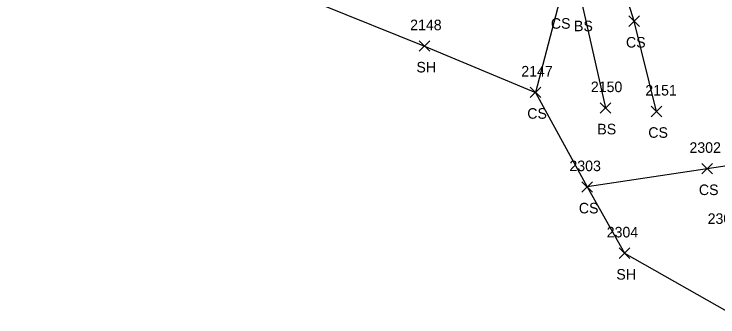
# Model space of a CAD drawing. Extents: x 1512665 to 1513714, y 110636 to 112816.
# Drawn here: x 1512781.5 to 1512914.5, y 110708.3 to 110765.6 of the extents above; entities that cross this region are included whole.
import ezdxf

# ---------------------------------------------------------------- set-up
doc = ezdxf.new("R2010")
doc.units = 0
for name, color, linetype in [('L_A', 7, 'Continuous'), ('L_I', 7, 'Continuous'), ('L_TIC', 7, 'Continuous'), ('LELB', 7, 'Continuous'), ('LSOGP', 7, 'Continuous')]:
    doc.layers.add(name, color=color, linetype=linetype)

msp = doc.modelspace()

# ---------------------------------------------------------------- linework, layer by layer
at = {"layer": 'L_TIC'}
for points in [[(1512897.68, 110763.29), (1512899.68, 110765.29)], [(1512899.68, 110763.29), (1512897.68, 110765.29)], [(1512858.02, 110758.58), (1512860.02, 110760.58)], [(1512860.02, 110758.58), (1512858.02, 110760.58)], [(1512879.03, 110749.81), (1512881.03, 110751.81)], [(1512881.03, 110749.81), (1512879.03, 110751.81)], [(1512892.27, 110746.85), (1512894.27, 110748.85)], [(1512894.27, 110746.85), (1512892.27, 110748.85)], [(1512901.91, 110746.2), (1512903.91, 110748.2)], [(1512903.91, 110746.2), (1512901.91, 110748.2)], [(1512911.47, 110735.35), (1512913.47, 110737.35)], [(1512913.47, 110735.35), (1512911.47, 110737.35)], [(1512888.78, 110731.88), (1512890.78, 110733.88)], [(1512890.78, 110731.88), (1512888.78, 110733.88)], [(1512895.83, 110719.33), (1512897.83, 110721.33)], [(1512897.83, 110719.33), (1512895.83, 110721.33)]]:
    msp.add_lwpolyline(points, dxfattribs=at)
at = {"layer": 'LELB'}
for points in [[(1512833.23, 110797.62), (1512854.29, 110791.85), (1512864.61, 110809.77), (1512876.39, 110789.5), (1512884.49, 110767.86), (1512880.03, 110750.81)], [(1512882.31, 110793.7), (1512888.86, 110767.38), (1512893.27, 110747.85)], [(1512902.91, 110747.2), (1512898.68, 110764.29), (1512894.99, 110776.22), (1512897.02, 110786.49), (1512915.92, 110779.17), (1512918.44, 110768.09), (1512924.56, 110757.29), (1512930.94, 110739.07), (1512912.47, 110736.35), (1512889.78, 110732.88)]]:
    msp.add_lwpolyline(points, dxfattribs=at)
at = {"layer": 'LSOGP'}
msp.add_lwpolyline([(1512677.75, 110879.68), (1512694.93, 110847.53), (1512720.01, 110832.5), (1512744.42, 110818.94), (1512769.04, 110811.74), (1512784.16, 110806.73), (1512800.09, 110794.66), (1512819.62, 110775.51), (1512859.02, 110759.58), (1512880.03, 110750.81), (1512889.78, 110732.88), (1512896.82, 110720.33), (1512918.08, 110708.27)], dxfattribs=at)

# ---------------------------------------------------------------- texts
at = {"layer": 'L_A'}
for s, p in [('CS', (1512882.93, 110762.86)), ('BS', (1512887.3, 110762.38)), ('CS', (1512897.13, 110759.29)), ('SH', (1512857.51, 110754.58)), ('CS', (1512878.47, 110745.81)), ('BS', (1512891.71, 110742.85)), ('CS', (1512901.35, 110742.2)), ('CS', (1512910.91, 110731.35)), ('CS', (1512888.22, 110727.88)), ('SH', (1512895.31, 110715.33))]:
    msp.add_text(s, height=2, dxfattribs=at).set_placement(p)
at = {"layer": 'L_I'}
for s, p in [('2148', (1512856.33, 110762.58)), ('2147', (1512877.34, 110753.81)), ('2150', (1512890.49, 110750.85)), ('2151', (1512900.79, 110750.2)), ('2302', (1512909.13, 110739.35)), ('2303', (1512886.44, 110735.88)), ('2305', (1512912.57, 110725.89)), ('2304', (1512893.49, 110723.33))]:
    msp.add_text(s, height=2, dxfattribs=at).set_placement(p)

doc.saveas('drawing.dxf')
